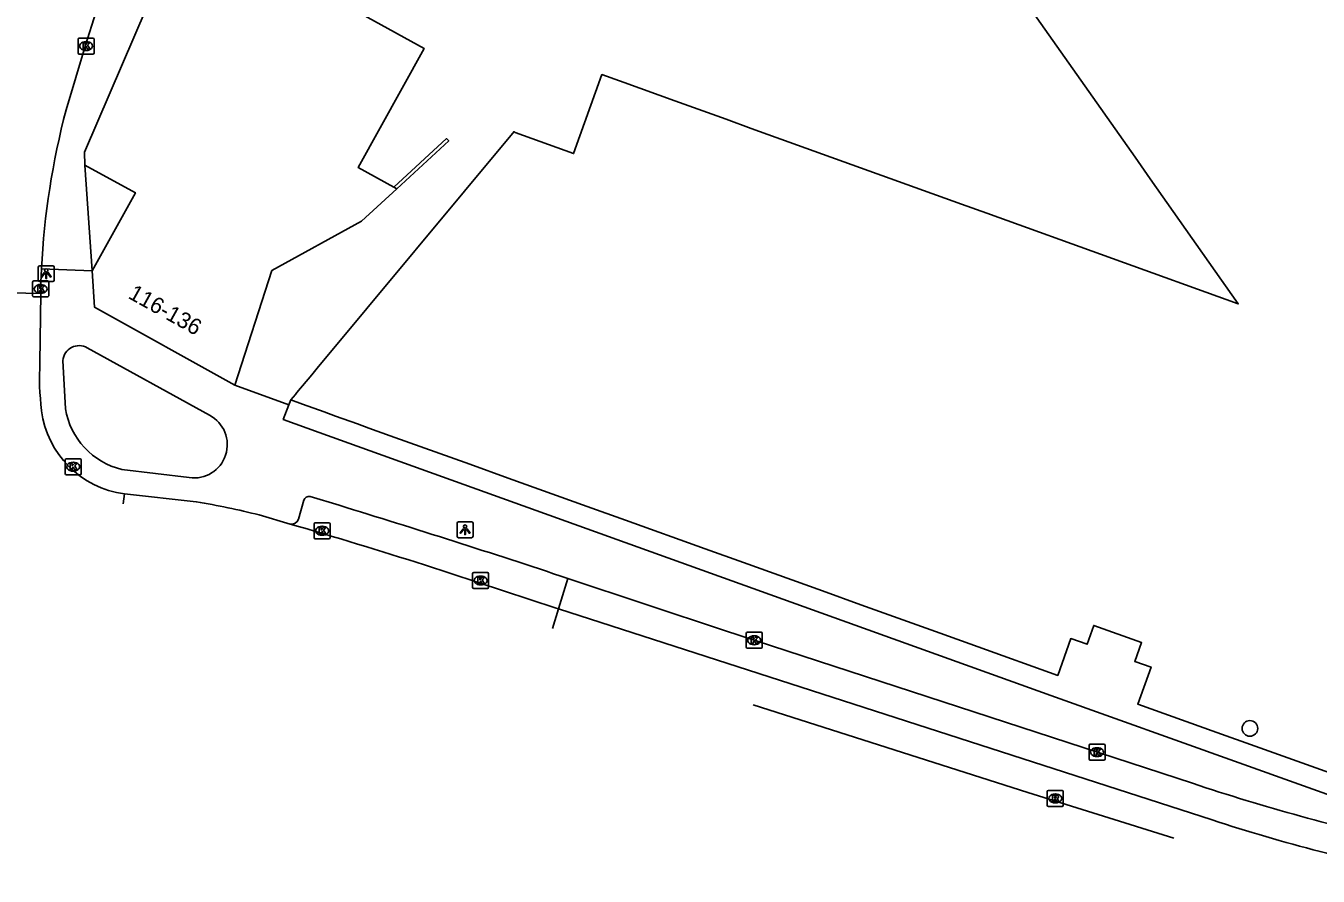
# Model space of a CAD drawing. Extents: x 159718 to 160783, y 383290 to 384030.
# Drawn here: x 160307.9 to 160388.6, y 383329.3 to 383382.4 of the extents above; entities that cross this region are included whole.
import ezdxf

# ---------------------------------------------------------------- set-up
doc = ezdxf.new("R2010")
doc.units = 0
for name, color, linetype in [('IMGEO_Boom', 7, 'Continuous'), ('IMGEO_Kolk', 7, 'Continuous'), ('IMGEO_Lichtpunt', 7, 'Continuous'), ('IMGEO_Muur', 7, 'Continuous'), ('IMGEO_Pand', 7, 'Continuous'), ('IMGEO_Pand_nummerreeks', 7, 'Continuous'), ('IMGEO_Pand_overbouw', 7, 'Continuous'), ('IMGEO_Parkeervlak_open', 7, 'Continuous'), ('IMGEO_Rijbaan_lokaal_gesloten', 7, 'Continuous'), ('IMGEO_Rijbaan_lokaal_open', 7, 'Continuous'), ('IMGEO_Rioolput', 7, 'Continuous'), ('IMGEO_Voetpad_open', 7, 'Continuous')]:
    doc.layers.add(name, color=color, linetype=linetype)

msp = doc.modelspace()

# ---------------------------------------------------------------- linework, layer by layer
at = {"layer": 'IMGEO_Boom'}
msp.add_circle((160384.315, 383338.521), 0.489, dxfattribs=at)
at = {"layer": 'IMGEO_Kolk'}
for p, q in [((160311.161, 383380.704), (160311.161, 383381.556)), ((160311.236, 383381.63), (160312.088, 383381.63)), ((160311.649, 383381.41), (160311.674, 383381.41)), ((160312.162, 383381.556), (160312.162, 383380.704)), ((160312.088, 383380.63), (160311.236, 383380.63)), ((160311.672, 383380.85), (160311.647, 383380.85)), ((160308.325, 383365.536), (160308.325, 383366.388)), ((160308.4, 383366.462), (160309.252, 383366.462)), ((160308.813, 383366.242), (160308.838, 383366.242)), ((160309.326, 383366.388), (160309.326, 383365.536)), ((160309.252, 383365.462), (160308.4, 383365.462)), ((160308.836, 383365.682), (160308.811, 383365.682)), ((160310.357, 383354.437), (160310.357, 383355.289)), ((160310.432, 383355.363), (160311.284, 383355.363)), ((160310.868, 383354.583), (160310.843, 383354.583)), ((160310.845, 383355.143), (160310.87, 383355.143)), ((160311.358, 383355.289), (160311.358, 383354.437)), ((160311.284, 383354.363), (160310.432, 383354.363)), ((160325.973, 383351.362), (160326.825, 383351.362)), ((160325.898, 383350.436), (160325.898, 383351.288)), ((160326.409, 383350.582), (160326.384, 383350.582)), ((160326.386, 383351.142), (160326.411, 383351.142)), ((160326.899, 383351.288), (160326.899, 383350.436)), ((160326.825, 383350.362), (160325.973, 383350.362)), ((160335.791, 383347.333), (160335.791, 383348.185)), ((160335.866, 383348.259), (160336.718, 383348.259)), ((160336.792, 383348.185), (160336.792, 383347.333)), ((160336.302, 383347.479), (160336.277, 383347.479)), ((160336.279, 383348.039), (160336.304, 383348.039)), ((160336.718, 383347.259), (160335.866, 383347.259)), ((160352.87, 383343.602), (160352.87, 383344.454)), ((160352.945, 383344.528), (160353.797, 383344.528)), ((160353.358, 383344.308), (160353.383, 383344.308)), ((160353.871, 383344.454), (160353.871, 383343.602)), ((160353.797, 383343.528), (160352.945, 383343.528)), ((160353.381, 383343.748), (160353.356, 383343.748)), ((160374.274, 383336.614), (160374.274, 383337.466)), ((160374.349, 383337.54), (160375.201, 383337.54)), ((160374.762, 383337.32), (160374.787, 383337.32)), ((160375.275, 383337.466), (160375.275, 383336.614)), ((160375.201, 383336.54), (160374.349, 383336.54)), ((160374.785, 383336.76), (160374.76, 383336.76))]:
    msp.add_line(p, q, dxfattribs=at)
for points in [[(160311.161, 383380.704), (160311.161, 383381.556)], [(160311.236, 383381.63), (160312.088, 383381.63)], [(160311.482, 383381.33), (160311.605, 383381.33), (160311.605, 383381.179), (160311.735, 383381.33), (160311.899, 383381.33), (160311.753, 383381.179), (160311.906, 383380.93), (160311.754, 383380.93), (160311.669, 383381.094), (160311.605, 383381.027), (160311.605, 383380.93), (160311.482, 383380.93), (160311.482, 383381.33)], [(160312.162, 383381.556), (160312.162, 383380.704)], [(160312.088, 383380.63), (160311.236, 383380.63)], [(160308.325, 383365.536), (160308.325, 383366.388)], [(160308.4, 383366.462), (160309.252, 383366.462)], [(160308.646, 383366.162), (160308.769, 383366.162), (160308.769, 383366.011), (160308.899, 383366.162), (160309.063, 383366.162), (160308.917, 383366.011), (160309.07, 383365.762), (160308.918, 383365.762), (160308.833, 383365.926), (160308.769, 383365.859), (160308.769, 383365.762), (160308.646, 383365.762), (160308.646, 383366.162)], [(160309.326, 383366.388), (160309.326, 383365.536)], [(160309.252, 383365.462), (160308.4, 383365.462)], [(160310.357, 383354.437), (160310.357, 383355.289)], [(160310.432, 383355.363), (160311.284, 383355.363)], [(160310.678, 383355.063), (160310.801, 383355.063), (160310.801, 383354.912), (160310.931, 383355.063), (160311.095, 383355.063), (160310.949, 383354.912), (160311.102, 383354.663), (160310.95, 383354.663), (160310.865, 383354.827), (160310.801, 383354.76), (160310.801, 383354.663), (160310.678, 383354.663), (160310.678, 383355.063)], [(160311.358, 383355.289), (160311.358, 383354.437)], [(160311.284, 383354.363), (160310.432, 383354.363)], [(160325.973, 383351.362), (160326.825, 383351.362)], [(160325.898, 383350.436), (160325.898, 383351.288)], [(160326.219, 383351.062), (160326.342, 383351.062), (160326.342, 383350.911), (160326.472, 383351.062), (160326.636, 383351.062), (160326.49, 383350.911), (160326.643, 383350.662), (160326.491, 383350.662), (160326.406, 383350.826), (160326.342, 383350.759), (160326.342, 383350.662), (160326.219, 383350.662), (160326.219, 383351.062)], [(160326.899, 383351.288), (160326.899, 383350.436)], [(160326.825, 383350.362), (160325.973, 383350.362)], [(160335.791, 383347.333), (160335.791, 383348.185)], [(160335.866, 383348.259), (160336.718, 383348.259)], [(160336.792, 383348.185), (160336.792, 383347.333)], [(160336.112, 383347.959), (160336.235, 383347.959), (160336.235, 383347.808), (160336.365, 383347.959), (160336.529, 383347.959), (160336.383, 383347.808), (160336.536, 383347.559), (160336.384, 383347.559), (160336.299, 383347.723), (160336.235, 383347.656), (160336.235, 383347.559), (160336.112, 383347.559), (160336.112, 383347.959)], [(160336.718, 383347.259), (160335.866, 383347.259)], [(160352.87, 383343.602), (160352.87, 383344.454)], [(160352.945, 383344.528), (160353.797, 383344.528)], [(160353.191, 383344.228), (160353.314, 383344.228), (160353.314, 383344.077), (160353.444, 383344.228), (160353.608, 383344.228), (160353.462, 383344.077), (160353.615, 383343.828), (160353.463, 383343.828), (160353.378, 383343.992), (160353.314, 383343.925), (160353.314, 383343.828), (160353.191, 383343.828), (160353.191, 383344.228)], [(160353.871, 383344.454), (160353.871, 383343.602)], [(160353.797, 383343.528), (160352.945, 383343.528)], [(160374.274, 383336.614), (160374.274, 383337.466)], [(160374.349, 383337.54), (160375.201, 383337.54)], [(160374.595, 383337.24), (160374.718, 383337.24), (160374.718, 383337.089), (160374.848, 383337.24), (160375.012, 383337.24), (160374.866, 383337.089), (160375.019, 383336.84), (160374.867, 383336.84), (160374.782, 383337.004), (160374.718, 383336.937), (160374.718, 383336.84), (160374.595, 383336.84), (160374.595, 383337.24)], [(160375.275, 383337.466), (160375.275, 383336.614)], [(160375.201, 383336.54), (160374.349, 383336.54)]]:
    msp.add_lwpolyline(points, dxfattribs=at)
for centre, start, end in [((160311.238, 383381.554), 91.55205, 178.44795), ((160311.238, 383381.554), 91.55205, 178.44795), ((160312.086, 383381.554), 1.55205, 88.44795), ((160312.086, 383381.554), 1.55205, 88.44795), ((160311.238, 383380.706), 181.55205, 268.44795), ((160311.238, 383380.706), 181.55205, 268.44795), ((160312.086, 383380.706), 271.55205, 358.44795), ((160312.086, 383380.706), 271.55205, 358.44795), ((160308.402, 383366.386), 91.55205, 178.44795), ((160308.402, 383366.386), 91.55205, 178.44795), ((160309.25, 383366.386), 1.55205, 88.44795), ((160309.25, 383366.386), 1.55205, 88.44795), ((160308.402, 383365.538), 181.55205, 268.44795), ((160308.402, 383365.538), 181.55205, 268.44795), ((160309.25, 383365.538), 271.55205, 358.44795), ((160309.25, 383365.538), 271.55205, 358.44795), ((160310.434, 383355.287), 91.55205, 178.44795), ((160310.434, 383355.287), 91.55205, 178.44795), ((160311.282, 383355.287), 1.55205, 88.44795), ((160311.282, 383355.287), 1.55205, 88.44795), ((160310.434, 383354.439), 181.55205, 268.44795), ((160310.434, 383354.439), 181.55205, 268.44795), ((160311.282, 383354.439), 271.55205, 358.44795), ((160311.282, 383354.439), 271.55205, 358.44795), ((160325.975, 383351.286), 91.55205, 178.44795), ((160325.975, 383351.286), 91.55205, 178.44795), ((160326.823, 383351.286), 1.55205, 88.44795), ((160326.823, 383351.286), 1.55205, 88.44795), ((160325.975, 383350.438), 181.55205, 268.44795), ((160325.975, 383350.438), 181.55205, 268.44795), ((160326.823, 383350.438), 271.55205, 358.44795), ((160326.823, 383350.438), 271.55205, 358.44795), ((160335.868, 383348.183), 91.55205, 178.44795), ((160335.868, 383348.183), 91.55205, 178.44795), ((160336.716, 383348.183), 1.55205, 88.44795), ((160336.716, 383348.183), 1.55205, 88.44795), ((160335.868, 383347.335), 181.55205, 268.44795), ((160335.868, 383347.335), 181.55205, 268.44795), ((160336.716, 383347.335), 271.55205, 358.44795), ((160336.716, 383347.335), 271.55205, 358.44795), ((160352.947, 383344.452), 91.55205, 178.44795), ((160352.947, 383344.452), 91.55205, 178.44795), ((160353.795, 383344.452), 1.55205, 88.44795), ((160353.795, 383344.452), 1.55205, 88.44795), ((160352.947, 383343.604), 181.55205, 268.44795), ((160352.947, 383343.604), 181.55205, 268.44795), ((160353.795, 383343.604), 271.55205, 358.44795), ((160353.795, 383343.604), 271.55205, 358.44795), ((160374.351, 383337.464), 91.55205, 178.44795), ((160374.351, 383337.464), 91.55205, 178.44795), ((160375.199, 383337.464), 1.55205, 88.44795), ((160375.199, 383337.464), 1.55205, 88.44795), ((160374.351, 383336.616), 181.55205, 268.44795), ((160374.351, 383336.616), 181.55205, 268.44795), ((160375.199, 383336.616), 271.55205, 358.44795), ((160375.199, 383336.616), 271.55205, 358.44795)]:
    msp.add_arc(centre, 0.0765, start, end, dxfattribs=at)
for centre, major_axis, ratio, start_param, end_param in [((160311.648, 383381.13), (-0.387, 0.002), 0.722429, 4.712389, 7.853982), ((160311.673, 383381.13), (-0.39, 0.002), 0.717154, 1.570796, 4.712389), ((160308.812, 383365.962), (-0.387, 0.002), 0.722429, 4.712389, 7.853982), ((160308.837, 383365.962), (-0.39, 0.002), 0.717154, 1.570796, 4.712389), ((160310.844, 383354.863), (-0.387, 0.002), 0.722429, 4.712389, 7.853982), ((160310.869, 383354.863), (-0.39, 0.002), 0.717154, 1.570796, 4.712389), ((160326.385, 383350.862), (-0.387, 0.002), 0.722429, 4.712389, 7.853982), ((160326.41, 383350.862), (-0.39, 0.002), 0.717154, 1.570796, 4.712389), ((160336.278, 383347.759), (-0.387, 0.002), 0.722429, 4.712389, 7.853982), ((160336.303, 383347.759), (-0.39, 0.002), 0.717154, 1.570796, 4.712389), ((160353.357, 383344.028), (-0.387, 0.002), 0.722429, 4.712389, 7.853982), ((160353.382, 383344.028), (-0.39, 0.002), 0.717154, 1.570796, 4.712389), ((160374.761, 383337.04), (-0.387, 0.002), 0.722429, 4.712389, 7.853982), ((160374.786, 383337.04), (-0.39, 0.002), 0.717154, 1.570796, 4.712389)]:
    msp.add_ellipse(centre, major_axis=major_axis, ratio=ratio, start_param=start_param, end_param=end_param, dxfattribs=at)
at = {"layer": 'IMGEO_Lichtpunt'}
for p, q in [((160308.675, 383367.322), (160308.675, 383366.515)), ((160308.675, 383367.322), (160308.675, 383366.515)), ((160309.577, 383367.417), (160308.769, 383367.417)), ((160309.577, 383367.417), (160308.769, 383367.417)), ((160309.671, 383366.515), (160309.671, 383367.322)), ((160309.671, 383366.515), (160309.671, 383367.322)), ((160308.769, 383366.421), (160309.577, 383366.421)), ((160308.769, 383366.421), (160309.577, 383366.421)), ((160335.725, 383351.426), (160334.917, 383351.426)), ((160335.725, 383351.426), (160334.917, 383351.426)), ((160334.823, 383351.331), (160334.823, 383350.524)), ((160334.823, 383351.331), (160334.823, 383350.524)), ((160335.819, 383350.524), (160335.819, 383351.331)), ((160335.819, 383350.524), (160335.819, 383351.331)), ((160334.917, 383350.43), (160335.725, 383350.43)), ((160334.917, 383350.43), (160335.725, 383350.43))]:
    msp.add_line(p, q, dxfattribs=at)
for points in [[(160309.049, 383366.986), (160309.088, 383366.958), (160308.9, 383366.696), (160308.862, 383366.723), (160309.049, 383366.986)], [(160309.151, 383366.938), (160309.198, 383366.938), (160309.198, 383366.616), (160309.151, 383366.616), (160309.151, 383366.938)], [(160309.261, 383366.958), (160309.299, 383366.985), (160309.486, 383366.723), (160309.447, 383366.695), (160309.261, 383366.958)], [(160335.197, 383350.995), (160335.236, 383350.967), (160335.048, 383350.705), (160335.01, 383350.732), (160335.197, 383350.995)], [(160335.299, 383350.947), (160335.346, 383350.947), (160335.346, 383350.625), (160335.299, 383350.625), (160335.299, 383350.947)], [(160335.409, 383350.967), (160335.447, 383350.994), (160335.634, 383350.732), (160335.595, 383350.704), (160335.409, 383350.967)]]:
    msp.add_lwpolyline(points, dxfattribs=at)
for centre in [(160309.174, 383367.12), (160335.322, 383351.129)]:
    msp.add_circle(centre, 0.0994, dxfattribs=at)
for centre, start, end in [((160308.769, 383367.322), 90, 180), ((160308.769, 383367.322), 90, 180), ((160309.577, 383367.322), 0, 90), ((160309.577, 383367.322), 0, 90), ((160308.769, 383366.515), 180, 270), ((160308.769, 383366.515), 180, 270), ((160309.577, 383366.515), 270, 0), ((160309.577, 383366.515), 270, 360), ((160334.917, 383351.331), 90, 180), ((160334.917, 383351.331), 90, 180), ((160335.725, 383351.331), 0, 90), ((160335.725, 383351.331), 0, 90), ((160334.917, 383350.524), 180, 270), ((160334.917, 383350.524), 180, 270), ((160335.725, 383350.524), 270, 0), ((160335.725, 383350.524), 270, 360)]:
    msp.add_arc(centre, 0.0946, start, end, dxfattribs=at)
at = {"layer": 'IMGEO_Muur'}
msp.add_lwpolyline([(160330.864, 383372.324), (160334.168, 383375.358), (160334.303, 383375.211), (160331.054, 383372.22)], dxfattribs=at)
at = {"layer": 'IMGEO_Pand'}
for points in [[(160312.038, 383367.09), (160314.742, 383371.969), (160311.589, 383373.702), (160311.554, 383374.506), (160315.48, 383383.61), (160316.304, 383383.157), (160319.229, 383388.45), (160319.536, 383388.281)], [(160319.536, 383388.281), (160332.763, 383380.989), (160328.643, 383373.555), (160330.864, 383372.324)], [(160324.437, 383359.034), (160324.726, 383359.382), (160324.821, 383359.495), (160325.747, 383360.609), (160326.096, 383361.027), (160338.377, 383375.789), (160338.451, 383375.728), (160342.092, 383374.42), (160343.864, 383379.354), (160344.965, 383378.958), (160345.247, 383378.856), (160348.417, 383377.713), (160351.627, 383376.556), (160353.19, 383375.993), (160366.32, 383371.26), (160367.888, 383370.695), (160383.593, 383365.033), (160378.099, 383372.84), (160377.153, 383374.184), (160369.124, 383385.592)], [(160331.054, 383372.22), (160328.865, 383370.206), (160323.258, 383367.115), (160320.956, 383359.966)], [(160331.054, 383372.22), (160330.864, 383372.324)], [(160320.956, 383359.966), (160312.191, 383364.819), (160312.038, 383367.09)], [(160324.437, 383359.034), (160325.169, 383358.771), (160326.527, 383358.283), (160327.242, 383358.026), (160328.602, 383357.537), (160329.318, 383357.28), (160330.653, 383356.8), (160335.609, 383355.019), (160338.002, 383354.159), (160342.947, 383352.382), (160345.343, 383351.521), (160350.307, 383349.737), (160352.697, 383348.878), (160357.637, 383347.105), (160360.034, 383346.245), (160364.972, 383344.473), (160367.361, 383343.616), (160372.319, 383341.837), (160373.13, 383344.137), (160374.151, 383343.774), (160374.57, 383344.951), (160377.549, 383343.882), (160377.131, 383342.711), (160378.148, 383342.348), (160377.313, 383340.045), (160382.25, 383338.277), (160384.649, 383337.417), (160389.604, 383335.643)]]:
    msp.add_lwpolyline(points, dxfattribs=at)
at = {"layer": 'IMGEO_Pand_overbouw'}
msp.add_lwpolyline([(160311.589, 383373.702), (160312.038, 383367.09), (160314.742, 383371.969)], close=True, dxfattribs=at)
msp.add_lwpolyline([(160389.604, 383335.643), (160384.649, 383337.417), (160382.25, 383338.277), (160377.313, 383340.045), (160378.148, 383342.348), (160377.131, 383342.711), (160377.549, 383343.882), (160374.57, 383344.951), (160374.151, 383343.774), (160373.13, 383344.137), (160372.319, 383341.837), (160367.361, 383343.616), (160364.972, 383344.473), (160360.034, 383346.245), (160357.637, 383347.105), (160352.697, 383348.878), (160350.307, 383349.737), (160345.343, 383351.521), (160342.947, 383352.382), (160338.002, 383354.159), (160335.609, 383355.019), (160330.653, 383356.8), (160329.318, 383357.28), (160328.602, 383357.537), (160327.242, 383358.026), (160326.527, 383358.283), (160325.169, 383358.771), (160324.437, 383359.034), (160324.316, 383358.719), (160323.969, 383357.813), (160326.207, 383357.008), (160371.888, 383340.582), (160395.395, 383332.177)], dxfattribs=at)
at = {"layer": 'IMGEO_Parkeervlak_open'}
msp.add_lwpolyline([(160341.149, 383345.985), (160341.74, 383347.889)], dxfattribs=at)
at = {"layer": 'IMGEO_Rijbaan_lokaal_gesloten'}
for points in [[(160308.831, 383365.683), (160303.2, 383365.803)], [(160308.783, 383361.372), (160308.831, 383365.683)], [(160313.978, 383352.541), (160314.052, 383353.178)], [(160318.544, 383352.677), (160314.052, 383353.178)], [(160324.406, 383351.284), (160322.469, 383351.854)], [(160341.149, 383345.985), (160341.006, 383346.031), (160332.792, 383348.731)], [(160340.77, 383344.767), (160341.149, 383345.985)], [(160381.952, 383332.805), (160341.149, 383345.985)], [(160379.561, 383331.676), (160370.452, 383334.526), (160353.298, 383339.998)]]:
    msp.add_lwpolyline(points, dxfattribs=at)
for centre, radius, start, end in [((160324.523, 383360.416), 15.769, 176.52277, 187.47564), ((160314.806, 383359.093), 5.963, 187.02455, 262.73188), ((160309.705, 383300.75), 52.674, 75.97607, 80.33932), ((160231.853, 383032.22), 332.216, 72.31193, 73.8238), ((160416.055, 383436.86), 109.501, 251.85392, 259.20448)]:
    msp.add_arc(centre, radius, start, end, dxfattribs=at)
at = {"layer": 'IMGEO_Rijbaan_lokaal_open'}
for points in [[(160312.912, 383385.292), (160311.627, 383381.183), (160310.416, 383377.156)], [(160308.831, 383365.683), (160308.839, 383366.376), (160308.874, 383367.222)]]:
    msp.add_lwpolyline(points, dxfattribs=at)
msp.add_arc((160358.212, 383364.65), 49.405, 165.33732, 177.0161, dxfattribs=at)
at = {"layer": 'IMGEO_Rioolput'}
for p, q in [((160371.665, 383333.726), (160371.665, 383334.578)), ((160371.74, 383334.652), (160372.592, 383334.652)), ((160372.153, 383334.432), (160372.178, 383334.432)), ((160372.666, 383334.578), (160372.666, 383333.726)), ((160372.592, 383333.652), (160371.74, 383333.652)), ((160372.176, 383333.872), (160372.151, 383333.872))]:
    msp.add_line(p, q, dxfattribs=at)
for points in [[(160371.665, 383333.726), (160371.665, 383334.578)], [(160371.74, 383334.652), (160372.592, 383334.652)], [(160372.666, 383334.578), (160372.666, 383333.726)], [(160372.592, 383333.652), (160371.74, 383333.652)], [(160372.254, 383334.35), (160372.002, 383334.352), (160372.002, 383333.952)], [(160372.002, 383333.952), (160372.126, 383333.952), (160372.126, 383334.114), (160372.137, 383334.114)], [(160372.18, 383334.271), (160372.126, 383334.271), (160372.126, 383334.19)], [(160372.126, 383334.19), (160372.178, 383334.19)], [(160372.184, 383334.085), (160372.255, 383333.952), (160372.395, 383333.952), (160372.33, 383334.078)]]:
    msp.add_lwpolyline(points, dxfattribs=at)
for centre, radius, start, end in [((160371.742, 383334.576), 0.0765, 91.55205, 178.44795), ((160371.742, 383334.576), 0.0765, 91.55205, 178.44795), ((160372.59, 383334.576), 0.0765, 1.55205, 88.44795), ((160372.59, 383334.576), 0.0765, 1.55205, 88.44795), ((160371.742, 383333.728), 0.0765, 181.55205, 268.44795), ((160371.742, 383333.728), 0.0765, 181.55205, 268.44795), ((160372.136, 383334.061), 0.0533, 26.02933, 88.69889), ((160372.162, 383334.379), 0.19, 274.7715, 282.96867), ((160372.186, 383334.175), 0.0964, 77.00612, 93.18647), ((160372.2, 383334.232), 0.0378, 276.66336, 79.67722), ((160372.253, 383334.24), 0.109, 350.36119, 89.41601), ((160372.251, 383334.24), 0.112, 277.58423, 350.98172), ((160372.235, 383334.025), 0.108, 29.51342, 73.79051), ((160372.59, 383333.728), 0.0765, 271.55205, 358.44795), ((160372.59, 383333.728), 0.0765, 271.55205, 358.44795)]:
    msp.add_arc(centre, radius, start, end, dxfattribs=at)
for centre, major_axis, ratio, start_param, end_param in [((160372.152, 383334.152), (-0.387, 0.002), 0.722429, 4.712389, 7.853982), ((160372.177, 383334.152), (-0.39, 0.002), 0.717154, 1.570796, 4.712389)]:
    msp.add_ellipse(centre, major_axis=major_axis, ratio=ratio, start_param=start_param, end_param=end_param, dxfattribs=at)
at = {"layer": 'IMGEO_Voetpad_open'}
for points in [[(160308.874, 383367.222), (160312.038, 383367.09)], [(160319.367, 383358.073), (160311.733, 383362.291)], [(160310.219, 383361.493), (160310.371, 383358.484)], [(160320.956, 383359.966), (160324.316, 383358.719), (160324.437, 383359.034)], [(160313.903, 383354.697), (160318.094, 383354.19)], [(160327.458, 383352.454), (160325.643, 383352.995)], [(160325.26, 383352.779), (160324.917, 383351.579)], [(160380.727, 383335.096), (160351.507, 383344.637), (160341.74, 383347.889)]]:
    msp.add_lwpolyline(points, dxfattribs=at)
for centre, radius, start, end in [((160311.227, 383361.416), 1.011, 59.96812, 175.61757), ((160314.979, 383359.241), 4.67, 189.33276, 256.67639), ((160318.405, 383356.238), 2.072, 261.36842, 62.32923), ((160325.565, 383352.686), 0.318, 75.76528, 163.078), ((160143.949, 382753.707), 626.238, 71.588475, 72.960324), ((160324.504, 383351.705), 0.432, 256.93291, 343.06272), ((160423.047, 383462.238), 134, 251.58953, 257.62901)]:
    msp.add_arc(centre, radius, start, end, dxfattribs=at)

# ---------------------------------------------------------------- texts
at = {"layer": 'IMGEO_Pand_nummerreeks'}
msp.add_text('116-136', height=1, rotation=330.83072, dxfattribs=at).set_placement((160314.229, 383365.419))

doc.saveas('drawing.dxf')
